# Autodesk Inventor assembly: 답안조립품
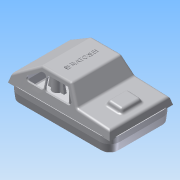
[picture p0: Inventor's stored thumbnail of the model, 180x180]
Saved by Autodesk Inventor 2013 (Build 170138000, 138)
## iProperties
Created: 2015-05
Part Number: 답안조립품
Document SubType Name: Assembly
Designer: Administrator
Author: Administrator
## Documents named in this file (5)
- C:\Documents and Settings\Administrator\바탕 화면\450507V1024\답안조립품.iam
- C:\Documents and Settings\Administrator\바탕 화면\450507V1024\1-본체.ipt
- C:\Documents and Settings\Administrator\바탕 화면\450507V1024\커버.ipt
- C:\Documents and Settings\Administrator\바탕 화면\450507V1024\바퀴.ipt
- C:\Documents and Settings\Administrator\바탕 화면\450507V1024\M4x10.ipt
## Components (5 placed, 2 different names)
1. 1-본체:1
2. M4x10:1
3. M4x10:2
4. M4x10:3
5. M4x10:4
